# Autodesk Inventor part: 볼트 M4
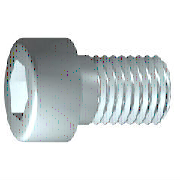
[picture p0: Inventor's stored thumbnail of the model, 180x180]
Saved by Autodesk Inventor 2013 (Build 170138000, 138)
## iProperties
IsCustomPart: 1
Created: 2015-10
Part Number: 볼트 M4
Material: 강, 연강
Description: 6각머리 태핑 나사
Document SubType Name: Modeling
Standard: KS B 1003
Designer: mdu
Standards Organization: KS
Language: ko-KR
Size Designation: M 4 x 16
Categories: <MemberInstance><Categories><Category DisplayName="조임쇠" InternalName="e4da775c-781d-43d5-af7c-5136215cf5a6" Mnemonic="FSTN"><Category DisplayName="볼트" InternalN
Density: 1 g/cm^3
Author: mdu
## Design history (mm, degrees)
sketch "스케치1"
  geometry: L1 (-1, 0)-(16, 0); L2 (16, 0)-(16, 2); L3 (16, 2)-(1.75, 2); L4 (1.75, 2)-(1.32, 2); L5 (1.32, 2)-(0, 2); L6 (0, 2)-(0, 3.5); L7 (0, 3.5)-(-4, 3.5); L8 (-4, 3.5)-(-4, 1.732); L9 (-4, 1.732)-(-2, 1.732); L10 (-2, 1.732)-(-1, 0); L11 (-8, 0)-(20, 0) reference; L12 (0, -0.7)-(0, 4.2) reference; L13 (1.75, 2)-(0, 2)
  constraints: 22 end point, 6 parallel, 2 collinear, 2 perpendicular, 1 horizontal, 1 point on line
  dimensions: "d1" = 14.25 distance from line of L3.end L2 (= GEL); "d2" = 0.42952 distance of L4.end L3.end (computed from GAL); "d3" = 4 distance between parallel lines of L8 L6 (= KOH); "d4" = 2 distance of L8.end L9.end (= INTI); "d5" = 60 deg angle of L10 L1; "d6" = 4 diameter of L3 L1 (= GD); "d7" = 4 diameter of L5 L1 (= BDM); "d8" = 3.4641 diameter of L9 L1 (= 1.1547 x SW); "d9" = 7 diameter of L7 L1 (= KOD); "d26" = 16 distance between parallel lines of L12 L2 (= NLG)
revolve "본체" sketch "스케치1" stored, may be unused: angle "d10" = 90 deg
sketch "스케치2"
  geometry: L1 (0, -4.9)-(0, 4.9) reference; L2 (-4.9, 0)-(4.9, 0) reference; L3 (1.732, 0)-(0.866, -1.5); L4 (0.866, -1.5)-(-0.866, -1.5); L5 (-0.866, -1.5)-(-1.732, 0); L6 (-1.732, 0)-(-0.866, 1.5); L7 (-0.866, 1.5)-(0.866, 1.5); L8 (0.866, 1.5)-(1.732, 0); 2 further points
  constraints: 12 end point, 1 coincident, 1 horizontal alignment, 1 point on line, 12 other
extrude "슬롯" join sketch "스케치2" stored distance "d11" = 10; taper "d12" = 0 deg
workplane "Work Plane1"
fillet "Fillet2" dims "d30" = 0.1 (= R)
body "Solid1"
fillet "모깎기1" dims "d17" = 0.4 (= RR)
feature "스레드" dims "d13" = 14.25 (= GEL), "d14" = 0
chamfer "모따기1" distance "d15" = 0.42941 (= -0.5 x SPD + 0.5 x GD); stored, may be unused: second distance "d16" = 0.42941 (= GUL), angle "d27" = 45 deg
other parameters: "GD" = 4 (= NND) [user parameter; used in 2 equation terms], "NLG" = 16 [user parameter; used in 1 equation term], "GEL" = 14.25 [user parameter; used in 2 equation terms], "KOD" = 7 [user parameter; used in 1 equation term], "KOH" = 4 [user parameter; used in 1 equation term], "INTI" = 2 [user parameter; used in 1 equation term], "GAL" = 0.42941 (= 0.61345 x PTC) [user parameter; used in 1 equation term], "GUL" = 0.42941 (= 0.61345 x PTC) [user parameter; used in 1 equation term], "BDM" = 4 (= NND) [user parameter; used in 1 equation term], "SW" = 3 [user parameter; used in 2 equation terms], "RR" = 0.4 [user parameter; used in 1 equation term], "SPD" = 3.14117 (= NND - 1.2269 x PTC) [user parameter; used in 1 equation term], "d19" = 0, "d28" = 0, "d29" = 0, "R" = 0.1 [user parameter; used in 1 equation term], "PHH" = 0.2 [user parameter], "GD1" = 3.14117 (= THREADDIA - 1.2269 x PTC) [user parameter], "THREADDIA" = 4 [user parameter; used in 1 equation term], "FAWI" = 45 deg [user parameter], "TPU" = 14.28571 (computed from PTC) [user parameter], "PTC" = 0.7 [user parameter; used in 5 equation terms], "NND" = 4 [user parameter; used in 3 equation terms], "TOA" = 30 deg [user parameter], "E0" = 3.465 (= 1.155 x SW) [user parameter]
